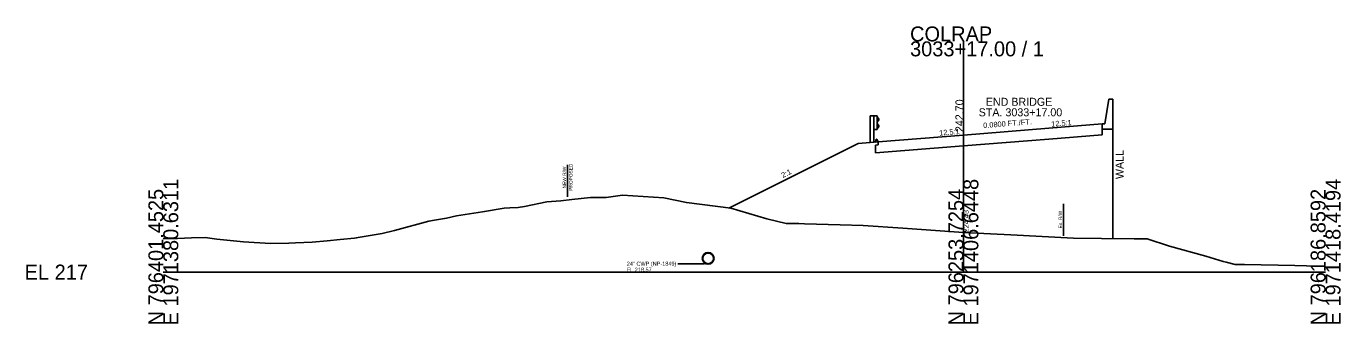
# Model space of a CAD drawing. Extents: x -26 to 1971073, y -10 to 796405.
# Drawn here: x -25.7 to 220.7, y 490.3 to 546.1 of the extents above; entities that cross this region are included whole.
import ezdxf

# ---------------------------------------------------------------- set-up
doc = ezdxf.new("R2010")
doc.units = 0
for name, color, linetype in [('RD_GPK_XS_Cell', 7, 'Continuous'), ('RD_XS_Base', 7, 'Continuous'), ('RD_XS_Box', 7, 'Continuous'), ('RD_XS_CurbTop', 7, 'Continuous'), ('RD_XS_ExGround', 7, 'Continuous'), ('RD_XS_ExRW', 7, 'Continuous'), ('RD_XS_GR', 7, 'Continuous'), ('RD_XS_MedBWall', 7, 'Continuous'), ('RD_XS_NewRW', 7, 'Continuous'), ('RD_XS_Pave', 7, 'Continuous'), ('RD_XS_PaveShd', 7, 'Continuous'), ('RD_XS_Pipe', 7, 'Continuous'), ('RD_XS_TieSlope', 7, 'Continuous'), ('RD_XS_TX_Elev_EX', 7, 'Continuous'), ('RD_XS_TX_Elev_PR', 7, 'Continuous'), ('RD_XS_TX_Notes', 7, 'Continuous'), ('RD_XS_TX_Slope', 7, 'Continuous')]:
    doc.layers.add(name, color=color, linetype=linetype)

msp = doc.modelspace()

# ---------------------------------------------------------------- linework, layer by layer
at = {"layer": 'RD_GPK_XS_Cell'}
for p, q in [((150, 500), (150, 543.27)), ((0, 500), (150, 500)), ((150, 500), (217.9, 500))]:
    msp.add_line(p, q, dxfattribs=at)
at = {"layer": 'RD_XS_Base'}
for p, q in [((176, 525.74), (176, 527.78)), ((150, 523.66), (166, 524.94)), ((166, 524.94), (176, 525.74)), ((133.5, 523.82), (134, 523.86)), ((133.5, 522.34), (133.5, 523.82)), ((150, 523.66), (133.5, 522.34)), ((134, 523.86), (134, 524.42))]:
    msp.add_line(p, q, dxfattribs=at)
at = {"layer": 'RD_XS_Box'}
msp.add_line((178, 526.78), (178, 506.26), dxfattribs=at)
at = {"layer": 'RD_XS_CurbTop'}
for p, q in [((133.53, 524.38), (133.59, 524.82)), ((134, 524.42), (133.53, 524.38)), ((134, 524.42), (133.75, 524.88))]:
    msp.add_line(p, q, dxfattribs=at)
msp.add_ellipse((133.68, 524.79), major_axis=(0, 0.131), ratio=0.686, start_param=5.388101, end_param=7.661995, dxfattribs=at)
at = {"layer": 'RD_XS_ExGround'}
msp.add_lwpolyline([(0, 506.32), (2.66, 506.31), (5.31, 506.39), (7.87, 506.46), (10.01, 506.18), (12.54, 505.91), (15.03, 505.64), (20.12, 505.33), (23.56, 505.45), (24.76, 505.48), (27.9, 505.62), (30.7, 505.87), (33.15, 506.13), (35.86, 506.34), (36.17, 506.39), (41.01, 507.25), (43.34, 507.81), (49.78, 509.55), (50.86, 509.74), (53.09, 510.13), (54.99, 510.54), (59.81, 511.29), (63.93, 511.98), (64.96, 512.05), (66.54, 512.12), (67.69, 512.27), (71.91, 513.15), (74.55, 513.34), (76.57, 513.59), (80.07, 513.98), (83.05, 514.01), (86.08, 514.42), (93.82, 513.91), (98.06, 513.03), (106.4, 511.96), (113.17, 509.96), (116.79, 509.12), (119.14, 509.09), (120.19, 509.05), (126.87, 508.86), (131.19, 508.75), (138.64, 508.22), (150, 507.43), (158.9, 506.97), (170.61, 506.36), (175.89, 506.28), (182.02, 506.23), (184.46, 506.22), (188.63, 504.86), (195.46, 502.99), (198.72, 501.98), (199.28, 501.83), (200.95, 501.43), (202.67, 501.4), (212.11, 501.23), (216.52, 501.12), (217.9, 501.16)], dxfattribs=at)
at = {"layer": 'RD_XS_ExRW'}
msp.add_line((168.75, 512.82), (168.75, 506.82), dxfattribs=at)
at = {"layer": 'RD_XS_GR'}
for p, q in [((133.19, 529.29), (132.52, 529.29)), ((132.52, 529.29), (132.52, 524.24)), ((133.85, 529.29), (133.19, 529.29)), ((133.19, 529.29), (133.19, 524.35)), ((133.85, 526.73), (133.85, 529.29)), ((133.85, 529.13), (134.12, 528.69)), ((134.12, 528.58), (133.85, 528.14)), ((134.12, 527.44), (133.85, 527.88)), ((134.12, 528.69), (134.12, 528.58)), ((134.12, 527.33), (134.12, 527.44)), ((133.85, 526.73), (133.19, 526.73)), ((133.85, 526.89), (134.12, 527.33))]:
    msp.add_line(p, q, dxfattribs=at)
at = {"layer": 'RD_XS_MedBWall'}
for p, q in [((176.5, 527.78), (177.25, 532.45)), ((177.25, 532.45), (178, 532.45)), ((178, 532.45), (178, 526.78)), ((176, 526.78), (176, 527.78)), ((176, 527.78), (176.5, 527.78)), ((178, 526.78), (176, 526.78))]:
    msp.add_line(p, q, dxfattribs=at)
at = {"layer": 'RD_XS_NewRW'}
msp.add_line((75.78, 520.14), (75.78, 514.14), dxfattribs=at)
at = {"layer": 'RD_XS_Pave'}
msp.add_line((150, 525.7), (166, 526.98), dxfattribs=at)
at = {"layer": 'RD_XS_PaveShd'}
for p, q in [((166, 526.98), (176, 527.78)), ((150, 525.7), (134, 524.42))]:
    msp.add_line(p, q, dxfattribs=at)
at = {"layer": 'RD_XS_Pipe'}
msp.add_line((101.47, 501.57), (96.47, 501.57), dxfattribs=at)
for radius in [1.1, 1]:
    msp.add_circle((102.14, 502.57), radius, dxfattribs=at)
at = {"layer": 'RD_XS_TieSlope'}
for p, q in [((130.25, 524.12), (106.02, 512.01)), ((134, 524.42), (130.25, 524.12))]:
    msp.add_line(p, q, dxfattribs=at)

# ---------------------------------------------------------------- texts
at = {"layer": 'RD_GPK_XS_Cell'}
for s, p in [('COLRAP', (140, 543.27)), ('3033+17.00 / 1', (140, 540.47)), ('EL 217', (-26, 498.6))]:
    msp.add_text(s, height=2.8, dxfattribs=at).set_placement(p)
for s, p in [('N 796401.4525', (0, 490)), ('E 1971380.6311', (2.8, 490)), ('N 796253.7254', (150, 490)), ('E 1971406.6448', (152.8, 490)), ('N 796186.8592', (217.9, 490)), ('E 1971418.4194', (220.7, 490))]:
    msp.add_text(s, height=2.8, rotation=90, dxfattribs=at).set_placement(p)
at = {"layer": 'RD_XS_ExRW'}
msp.add_text('Ex. R/W ', height=0.65, rotation=90, dxfattribs=at).set_placement((168.5, 508.2))
at = {"layer": 'RD_XS_NewRW'}
for s, p in [('PROPOSED', (76.72, 515.25)), ('NEW R/W ', (75.51, 515.7))]:
    msp.add_text(s, height=0.65, rotation=90, dxfattribs=at).set_placement(p)
at = {"layer": 'RD_XS_Pipe'}
for s, p in [('24" CWP (NP-1849)', (86.89, 501.19)), ('FL 218.57', (86.89, 500.07))]:
    msp.add_text(s, height=0.75, dxfattribs=at).set_placement(p)
at = {"layer": 'RD_XS_TX_Elev_EX'}
msp.add_text('224.43', height=1, rotation=90, dxfattribs=at).set_placement((151, 507.43))
at = {"layer": 'RD_XS_TX_Elev_PR'}
msp.add_text(' 242.70', height=1.5, rotation=90, dxfattribs=at).set_placement((150, 525.7))
at = {"layer": 'RD_XS_TX_Notes'}
for s, p in [('END BRIDGE', (154.19, 531.19)), ('STA. 3033+17.00', (152.86, 529.22))]:
    msp.add_text(s, height=1.5, dxfattribs=at).set_placement(p)
msp.add_text('WALL', height=1.5, rotation=90, dxfattribs=at).set_placement((180.03, 517.44))
at = {"layer": 'RD_XS_TX_Slope'}
for s, rotation, p in [('0.0800 FT./FT.', 4.5739, (153.75, 527)), ('12.5:1', 4.5739, (166.5, 527.27)), ('12.5:1', 4.5739, (145.5, 525.59)), ('2:1', 26.5651, (116.16, 517.64))]:
    msp.add_text(s, height=1, rotation=rotation, dxfattribs=at).set_placement(p)

doc.saveas('drawing.dxf')
